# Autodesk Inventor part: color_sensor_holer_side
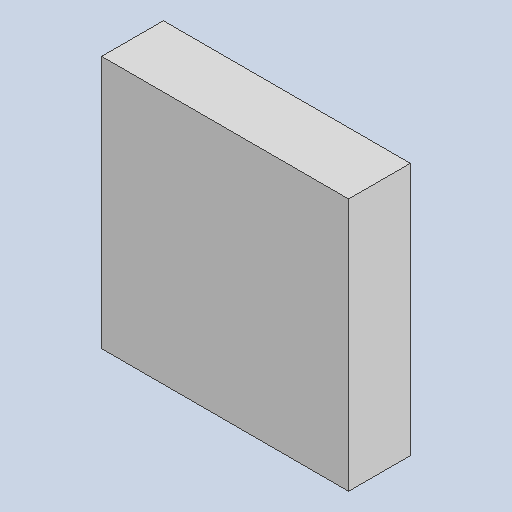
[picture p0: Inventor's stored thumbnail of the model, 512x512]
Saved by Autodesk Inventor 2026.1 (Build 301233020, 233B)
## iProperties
Created: 2026-10
Part Number: color_sensor_holer_side
Material: Generic
Document SubType Name: Modeling
Designer: alolo
Density: 1 g/cm^3
Appearance: Default
Author: alolo
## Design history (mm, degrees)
sketch "Sketch1"
  geometry: L1 (0, 0)-(20, 0); L2 (20, 0)-(20, 20.5); L3 (20, 20.5)-(0, 20.5); L4 (0, 20.5)-(0, 0)
  constraints: 8 end point, 2 parallel, 1 horizontal, 1 perpendicular
  dimensions: "d0" = 20 distance of L3.end L2.end; "d1" = 20.5 distance of L2.end L1.end
extrude "Extrusion1" new body sketch "Sketch1" distance "d2" = 5 (= wood_thickness); taper "d3" = 0 deg
body "Solid1"
other parameters: "slide_length" = 195 [user parameter], "slide_angle" = 7 deg [user parameter], "slide_width" = 65 [user parameter], "wood_thickness" = 5 [user parameter; used in 1 equation term], "aclyric_thickness" = 6 [user parameter]
